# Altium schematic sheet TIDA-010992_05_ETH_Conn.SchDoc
size 431 x 279 mm; Date: Not shown in title block; ApprovedBy: Not shown in title block; CheckedBy: Not shown in title block; Author: Not shown in title block; CompanyName: Not shown in title block; Engineer: Not shown in title block; Organization: Not shown in title block; Address1: Not shown in title block; Address2: Not shown in title block; Address3: Not shown in title block; Address4: Not shown in title block; DocumentNumber: 5; Revision: Use project parameter SCH_Rev; SheetNumber: 5; SheetTotal: 13; PageSetup: Record=PageOptions¦CenterHorizontal=True¦CenterVertical=True¦PrintScale=1.00¦XCorrection=1.00¦YCorrection=1.00¦PrintKind=0¦BorderSize=5000000¦LeftOffset=0¦BottomOffset=0¦Orientation=2¦PaperLength=1000¦PaperWidth=1000¦Scale=100¦PaperSource=15¦PrintQuality=600¦MediaType=1¦DitherType=10¦PaperKind=Letter¦PrintScaleMode=1
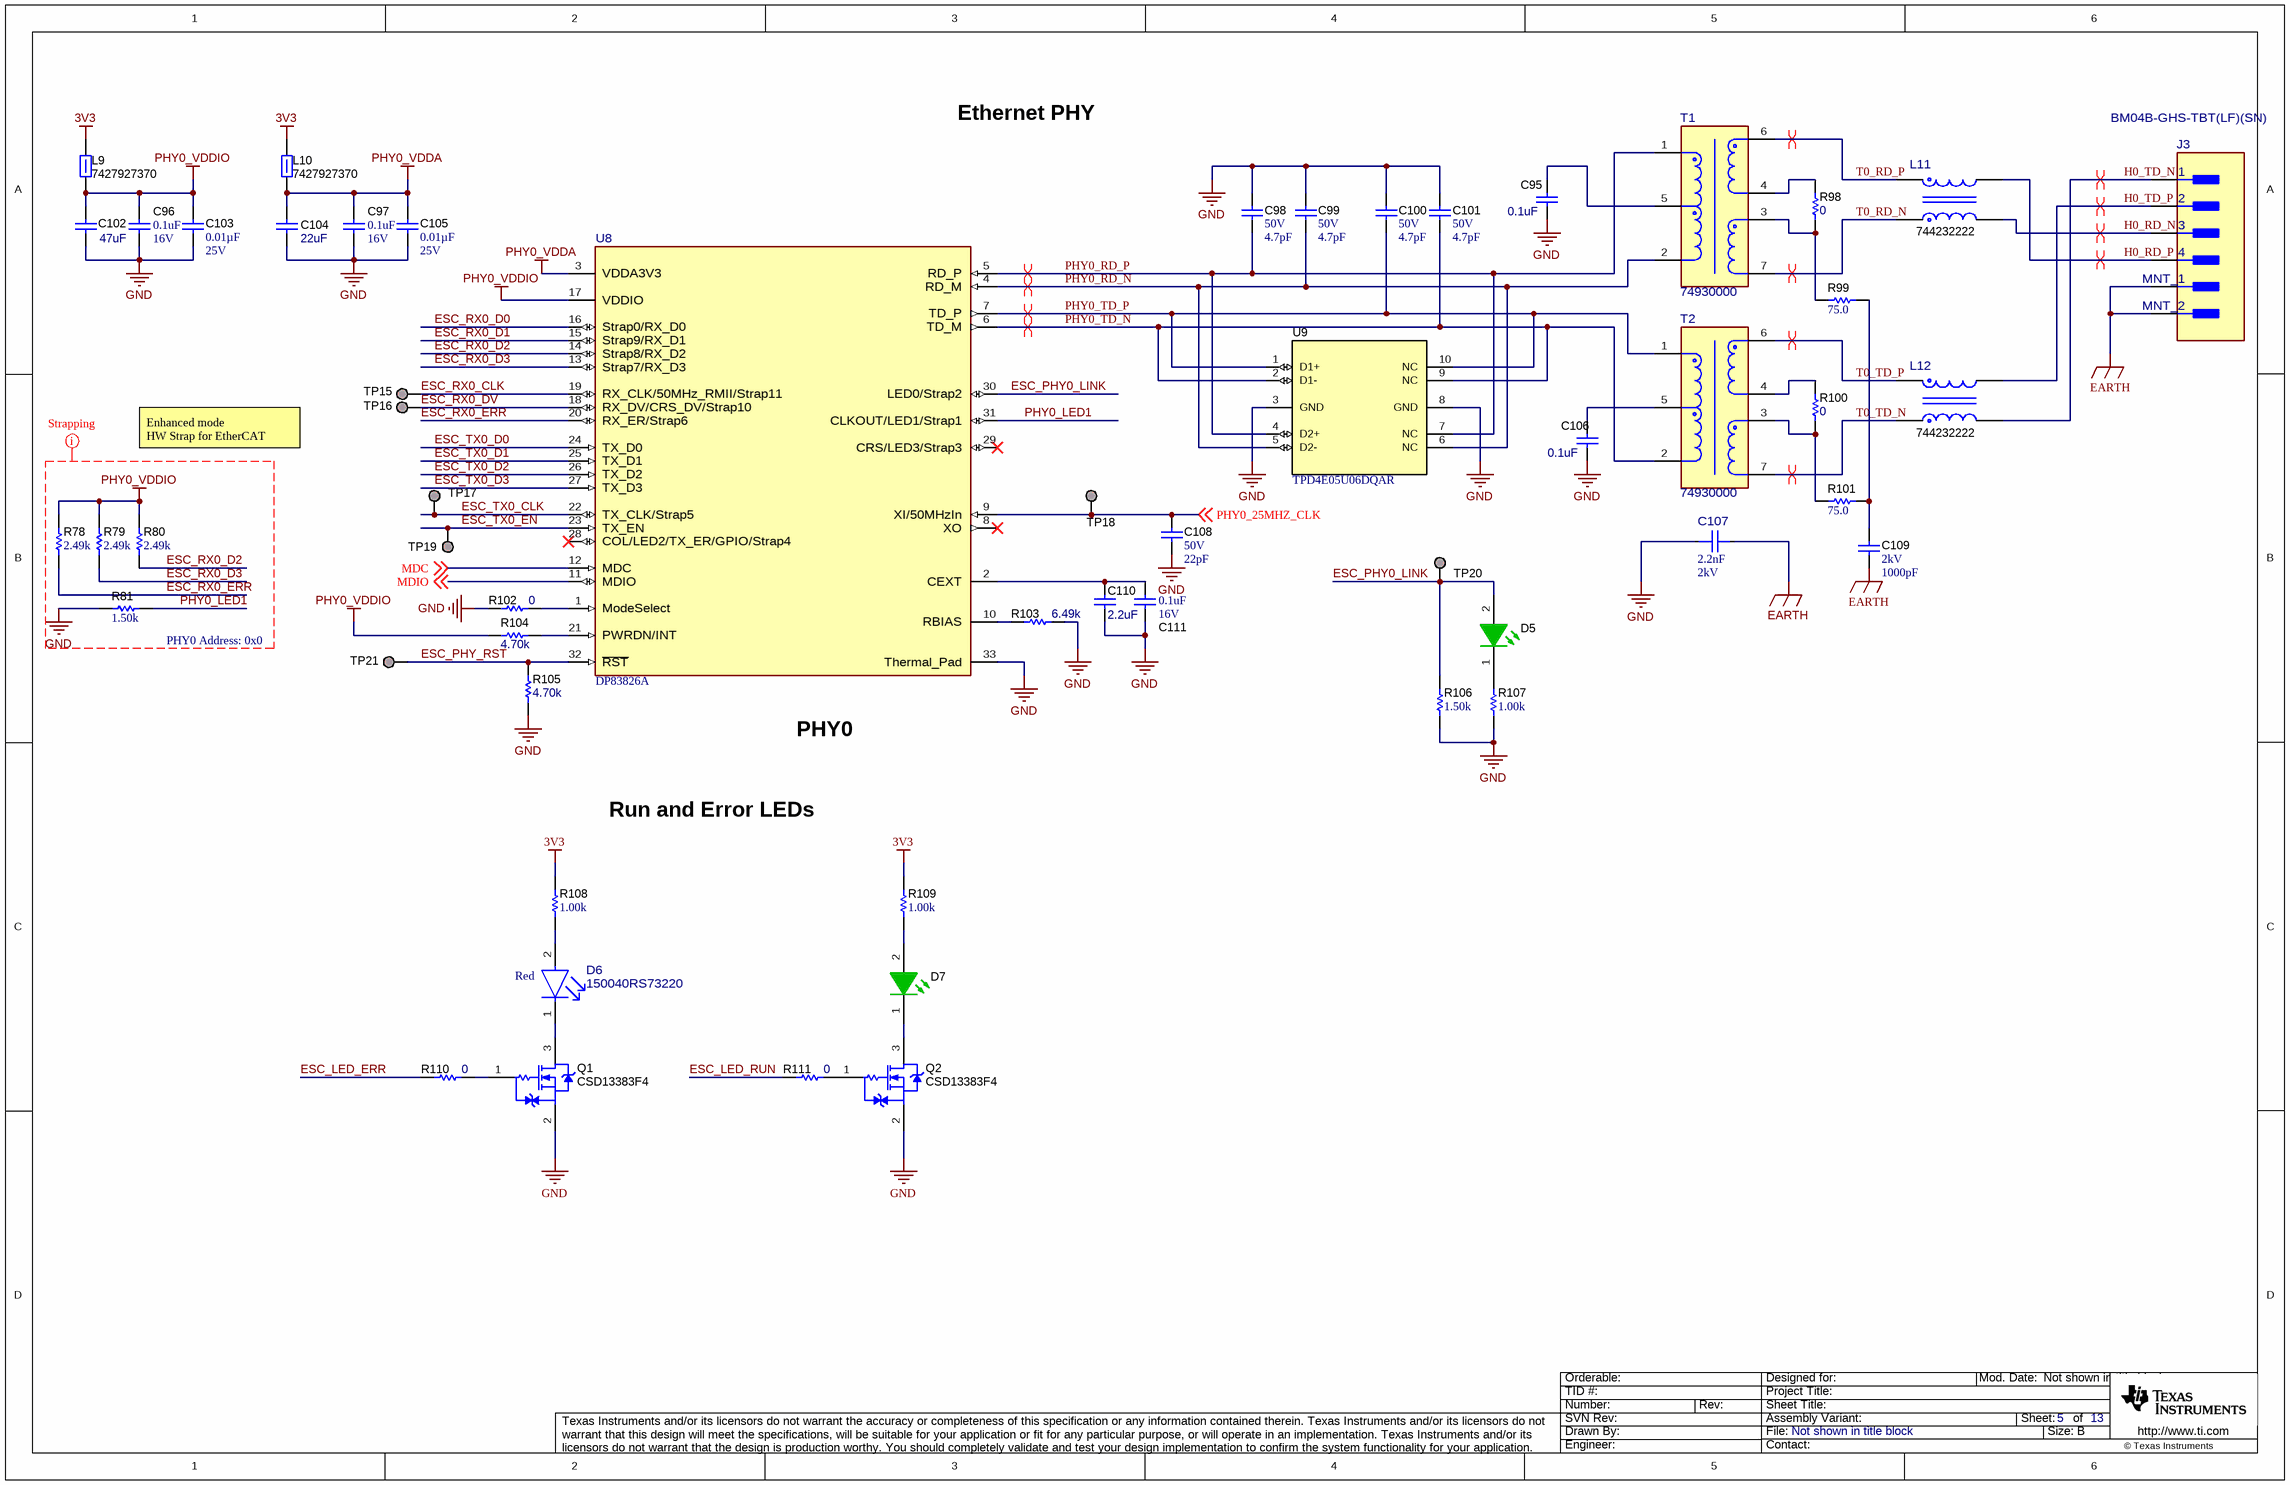
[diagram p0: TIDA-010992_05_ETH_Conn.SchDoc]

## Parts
C95  ValueDisplayed: 0.1uF  [0402]  (hidden comment: 885012205037)
C96  VDC_V: 16V  ValueDisplayed: 0.1uF  [0201]  (hidden comment: GRM033Z71C104KE14D)
C97  VDC_V: 16V  ValueDisplayed: 0.1uF  [0201]  (hidden comment: GRM033Z71C104KE14D)
C98  VDC_V: 50V  ValueDisplayed: 4.7pF  [0201_033]  (hidden comment: GRM0335C1H4R7BA01D)
C99  VDC_V: 50V  ValueDisplayed: 4.7pF  [0201_033]  (hidden comment: GRM0335C1H4R7BA01D)
C100  VDC_V: 50V  ValueDisplayed: 4.7pF  [0201_033]  (hidden comment: GRM0335C1H4R7BA01D)
C101  VDC_V: 50V  ValueDisplayed: 4.7pF  [0201_033]  (hidden comment: GRM0335C1H4R7BA01D)
C102  ValueDisplayed: 47uF  [0603]  (hidden comment: GRM188R60J476ME15D)
C103  ValueDisplayed: 0.01µF  VDC_V: 25V  [0201]  (hidden comment: GRM033R71E103KE14D)
C104  ValueDisplayed: 22uF  [0603]  (hidden comment: GRM188R61A226ME15D)
C105  ValueDisplayed: 0.01µF  VDC_V: 25V  [0201]  (hidden comment: GRM033R71E103KE14D)
C106  ValueDisplayed: 0.1uF  [0402]  (hidden comment: 885012205037)
C107  ValueDisplayed: 2.2nF  VDC_V: 2kV  [FP-1206Y2K00222KET_1206-MFG]  (hidden comment: 1206Y2K00222KET)
C108  VDC_V: 50V  ValueDisplayed: 22pF  [0402]  (hidden comment: CL05C220JB5NNNC)
C109  VDC_V: 2kV  ValueDisplayed: 1000pF  [1206_180]  (hidden comment: C1206C102KGRACAUTO)
C110  ValueDisplayed: 2.2uF  [0402_065]  (hidden comment: C1005X5R1V225K050BC)
C111  VDC_V: 16V  ValueDisplayed: 0.1uF  [0201]  (hidden comment: GRM033Z71C104KE14D)
D5  150040GS73240  [WL-SMCC_0402_Green]  (value not drawn)
D6  150040RS73220  Color: Red  [FP-150040RS73220_0402-MFG]
D7  150040GS73240  [WL-SMCC_0402_Green]  (value not drawn)
J3  BM04B-GHS-TBT(LF)(SN)  [FP-BM04B-GHS-TBT(LF)(SN)_HDR4-MFG]
L9  7427927370  [0402]
L10  7427927370  [0402]
L11  744232222  [FP-744232222_SMT4_3MM2_1MM6-MFG]
L12  744232222  [FP-744232222_SMT4_3MM2_1MM6-MFG]
Q1  CSD13383F4  [YJC0003A]
Q2  CSD13383F4  [YJC0003A]
R78  ValueDisplayed: 2.49k  [0201]  (hidden comment: RC0201FR-072K49L)
R79  ValueDisplayed: 2.49k  [0201]  (hidden comment: RC0201FR-072K49L)
R80  ValueDisplayed: 2.49k  [0201]  (hidden comment: RC0201FR-072K49L)
R81  ValueDisplayed: 1.50k  [0201]  (hidden comment: RK73H1HTTC1501F)
R98  ValueDisplayed: 0  [0402]  (hidden comment: CRCW04020000Z0EDHP)
R99  ValueDisplayed: 75.0  [0402]  (hidden comment: CRCW040275R0FKED)
R100  ValueDisplayed: 0  [0402]  (hidden comment: CRCW04020000Z0EDHP)
R101  ValueDisplayed: 75.0  [0402]  (hidden comment: CRCW040275R0FKED)
R102  ValueDisplayed: 0  [0402]  (hidden comment: CRCW04020000Z0EDHP)
R103  ValueDisplayed: 6.49k  [0402]  (hidden comment: CRCW04026K49FKED)
R104  ValueDisplayed: 4.70k  [0402]  (hidden comment: CRG0402F4K7)
R105  ValueDisplayed: 4.70k  [0402]  (hidden comment: CRG0402F4K7)
R106  ValueDisplayed: 1.50k  [0402]  (hidden comment: CRCW04021K50FKED)
R107  ValueDisplayed: 1.00k  [0402]  (hidden comment: CRCW04021K00FKED)
R108  ValueDisplayed: 1.00k  [0402]  (hidden comment: RC0402FR-071KL)
R109  ValueDisplayed: 1.00k  [0402]  (hidden comment: RC0402FR-071KL)
R110  ValueDisplayed: 0  [0402]  (hidden comment: CRCW04020000Z0EDHP)
R111  ValueDisplayed: 0  [0402]  (hidden comment: CRCW04020000Z0EDHP)
T1  74930000  [FP-74930000_SMT_4MM7_3MM22-MFG]
T2  74930000  [FP-74930000_SMT_4MM7_3MM22-MFG]
TP15  TESTPOINT  [TP_25MIL-SMT]  (value not drawn)  (no BOM)
TP16  TESTPOINT  [TP_25MIL-SMT]  (value not drawn)  (no BOM)
TP17  TESTPOINT  [TP_25MIL-SMT]  (value not drawn)  (no BOM)
TP18  TP_SM_1MM  [TP_SM_1MM]  (value not drawn)  (no BOM)
TP19  TESTPOINT  [TP_25MIL-SMT]  (value not drawn)  (no BOM)
TP20  TESTPOINT  [TP_25MIL-SMT]  (value not drawn)  (no BOM)
TP21  TESTPOINT  [TP_25MIL-SMT]  (value not drawn)  (no BOM)
U8  DP83826A  [RHB0032M-MFG]
U9  TPD4E05U06DQAR  [DQA0010A]

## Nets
3V3: L9.2 L10.2 R108.2 R109.2
EARTH: C107.2 C109.2 J3.5(MNT_1) J3.6(MNT_2)
GND: C95.2 C96.2 C97.2 C98.1 C99.1 C100.1 C101.1 C102.2 C103.2 C104.2 C105.2 C106.2 C107.1 C108.2 C110.2 C111.2 Q1.2(S) Q2.2(S) R81.1 R102.1 R103.2 R105.1 R106.2 R107.1 U8.33(Thermal_Pad) U9.3(GND) U9.8(GND)
PHY0_VDDA: C97.1 C104.1 C105.1 L10.1 U8.3(VDDA3V3)
PHY0_VDDIO: C96.1 C102.1 C103.1 L9.1 R78.2 R79.2 R80.2 R104.1 U8.17(VDDIO)
ESC_LED_ERR: R110.1
ESC_LED_RUN: R111.1
ESC_PHY0_LINK: D5.2(A) R106.1 TP20.1 U8.30(LED0/Strap2)
ESC_PHY_RST: R105.2 TP21.1 U8.32(~{RST})
ESC_RX0_CLK: TP15.1 U8.19(RX_CLK/50MHz_RMII/Strap11)
ESC_RX0_D0: U8.16(Strap0/RX_D0)
ESC_RX0_D1: U8.15(Strap9/RX_D1)
ESC_RX0_D2: R80.1 U8.14(Strap8/RX_D2)
ESC_RX0_D3: R79.1 U8.13(Strap7/RX_D3)
ESC_RX0_DV: TP16.1 U8.18(RX_DV/CRS_DV/Strap10)
ESC_RX0_ERR: R78.1 U8.20(RX_ER/Strap6)
ESC_TX0_CLK: TP17.1 U8.22(TX_CLK/Strap5)
ESC_TX0_D0: U8.24(TX_D0)
ESC_TX0_D1: U8.25(TX_D1)
ESC_TX0_D2: U8.26(TX_D2)
ESC_TX0_D3: U8.27(TX_D3)
ESC_TX0_EN: TP19.1 U8.23(TX_EN)
H0_RD_N: J3.3 L11.2
H0_RD_P: J3.4 L11.3
H0_TD_N: J3.1 L12.2
H0_TD_P: J3.2 L12.3
MDC: U8.12(MDC) ; off-sheet MDC
MDIO: U8.11(MDIO) ; off-sheet MDIO
PHY0_25MHZ_CLK: C108.1 TP18.1 U8.9(XI/50MHzIn) ; off-sheet PHY0_25MHZ_CLK
PHY0_LED1: R81.2 U8.31(CLKOUT/LED1/Strap1)
PHY0_RD_N: C99.2 T1.2 U8.4(RD_M) U9.5(D2-) U9.6(NC)
PHY0_RD_P: C98.2 T1.1 U8.5(RD_P) U9.4(D2+) U9.7(NC)
PHY0_TD_N: C101.2 T2.2 U8.6(TD_M) U9.2(D1-) U9.9(NC)
PHY0_TD_P: C100.2 T2.1 U8.7(TD_P) U9.1(D1+) U9.10(NC)
T0_RD_N: L11.1 T1.7
T0_RD_P: L11.4 T1.6
T0_TD_N: L12.1 T2.7
T0_TD_P: L12.4 T2.6
NetC95_1: C95.1 T1.5
NetC106_1: C106.1 T2.5
NetC109_1: C109.1 R99.2 R101.2
NetC110_1: C110.1 C111.1 U8.2(CEXT)
NetD5_1: D5.1(K) R107.2
NetD6_1: D6.1(CATHODE) Q1.3(D)
NetD6_2: D6.2(ANODE) R108.1
NetD7_1: D7.1(K) Q2.3(D)
NetD7_2: D7.2(A) R109.1
NetQ1_1: Q1.1(G) R110.2
NetQ2_1: Q2.1(G) R111.2
NetR98_1: R98.1 R99.1 T1.3
NetR98_2: R98.2 T1.4
NetR100_1: R100.1 R101.1 T2.3
NetR100_2: R100.2 T2.4
NetR102_2: R102.2 U8.1(ModeSelect)
NetR103_1: R103.1 U8.10(RBIAS)
NetR104_2: R104.2 U8.21(PWRDN/INT)

Not connected (* = marked no-connect by the designer): U8 8(XO)* 28(COL/LED2/TX_ER/GPIO/Strap4)* 29(CRS/LED3/Strap3)*

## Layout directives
differential pair: H0_RD_N, H0_RD_P, H0_TD_N, H0_TD_P, PHY0_RD_N, PHY0_RD_P, PHY0_TD_N, PHY0_TD_P, T0_RD_N, T0_RD_P, T0_TD_N, T0_TD_P
mark named Strapping: ESC_RX0_D2, ESC_RX0_D3, ESC_RX0_ERR, GND, PHY0_LED1, PHY0_VDDIO

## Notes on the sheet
- Ethernet PHY
- Enhanced mode
  HW Strap for EtherCAT setting
- (near R81) PHY0 Address: 0x0
- PHY0
- Run and Error LEDs

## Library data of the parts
C95 C106 = CMP-0006228-2: CAP, CERM, 0.1 uF, 16 V, +/- 10%, X7R, 0402; Manufacturer: Wurth Elektronik; TaMin_C: -55°C; Polarized: N; SizeAreaWB_mm2: 3; Value1: Unknown; U/M: EA; Value: 0.1uF; TaMax_C: 125°C; SizeZ_mm: 0.6; SizeX_mm: 1; SizeY_mm: 0.5; Value2: 16V; Cap_F: 100nF; AEC Category: Q200
C96 C97 C111 = CMP-0064970-1: CAP, CERM, 0.1 uF, 16 V,+/- 10%, X7R, 0201; Manufacturer: MuRata; TaMin_C: -55°C; Polarized: N; SizeAreaWB_mm2: 2.08; Value1: Unknown; U/M: EA; Value: 0.1uF; TaMax_C: 125°C; SizeZ_mm: 0.26; SizeX_mm: 0.6; SizeY_mm: 0.3; SizeArea_mm2: 0.18; Cap_F: 100nF; AEC Category: Q200
C98-C101 = CMP-0080076-1: CAP, CERM, 4.7 pF, 50 V,+/- 3%, C0G/NP0, 0201; Manufacturer: MuRata; TaMin_C: -55°C; Polarized: N; SizeAreaWB_mm2: 2.08; U/M: EA; Value: 4.7pF; TaMax_C: 125°C; SizeZ_mm: 0.33; SizeX_mm: 0.6; SizeY_mm: 0.3; Cap_Case: 0201; SizeArea_mm2: 0.18; AEC Category: Q200
C102 = CMP-0007313-5: CAP, CERM, 47 uF, 6.3 V, +/- 20%, X5R, 0603; Manufacturer: MuRata; TaMin_C: -55°C; Polarized: N; SizeAreaWB_mm2: 4.68; Value1: Unknown; U/M: EA; Value: 47uF; TaMax_C: 85°C; SizeZ_mm: 1; SizeX_mm: 1.6; SizeY_mm: 0.8; Value2: 6.3V; SizeArea_mm2: 1.28; Cap_F: 47µF; AEC Category: Q200
C103 C105 = CMP-0860568-1: CAP, CERM, 0.01 µF, 25 V,+/- 10%, X7R, 0201; Manufacturer: MuRata; U/M: EA; TaMax_C: 125°C; SizeZ_mm: 0.26; AEC Qualified: N; TaMin_C: -55°C; SizeY_mm: 0.3; AEC Category: Q200; SizeAreaWB_mm2: 2.08; Cap_F: 10nF; SizeX_mm: 0.6; Value: 0.01uF; SizeArea_mm2: 0.18
C104 = CMP-0007324-5: CAP, CERM, 22 uF, 10 V, +/- 20%, X5R, 0603; Manufacturer: MuRata; TaMin_C: -55°C; Polarized: N; SizeAreaWB_mm2: 4.68; Value1: Unknown; U/M: EA; Value: 22uF; TaMax_C: 85°C; SizeZ_mm: 1; SizeX_mm: 1.6; SizeY_mm: 0.8; Value2: 10V; SizeArea_mm2: 1.28; Cap_F: 22µF; AEC Category: Q200
C107 = CMP-0090879-1: 2200pF ±10% 2000V (2kV) Ceramic Capacitor X7R (2R1) 1206 (3216 Metric); Manufacturer: Knowles Syfer; TempCo: 15%; AEC Grade: Grade 1; AEC Qualified: Yes; SizeZ_mm: 1.7mm; Value: 2.2nF
C108 = CMP-0085851-1: CAP, CERM, 22 pF, 50 V,+/- 5%, C0G/NP0, 0402; Manufacturer: Walsin; AEC Qualified: N; TaMax_C: 125°C; SizeX_mm: 1; Value: 22pF; SizeZ_mm: 0.6; AEC Category: Q200; TaMin_C: -55°C; SizeArea_mm2: 0.5; SizeAreaWB_mm2: 3; U/M: EA
C109 = CMP-0008579-2: CAP, CERM, 1000 pF, 2000 V, +/- 10%, X7R, AEC-Q200 Grade 1, 1206; Manufacturer: Kemet; TaMin_C: -55°C; Polarized: N; SizeAreaWB_mm2: 10.92; Value1: Unknown; U/M: EA; Value: 1000pF; TaMax_C: 125°C; SizeZ_mm: 1.8; SizeX_mm: 3.2; SizeY_mm: 1.6; Cap_Case: 1206; Value2: 2000V; SizeArea_mm2: 5.12; AEC Qualified: Y; Cap_F: 1nF; AEC Grade: 1; AEC Category: Q200
C110 = CMP-0006283-2: CAP, CERM, 2.2 uF, 35 V, +/- 10%, X5R, 0402; Manufacturer: TDK; TaMin_C: -55°C; ESR_ohm: 5.925m; Polarized: N; SizeAreaWB_mm2: 3; Value1: 0.005925 ohm; U/M: EA; Value: 2.2uF; TaMax_C: 85°C; SizeZ_mm: 0.65; SizeX_mm: 1; SizeY_mm: 0.5; Value2: 35V; Cap_F: 2.2µF; IRMS_A: 2.0559A; AEC Category: Q200
D5 D7 = CMP-0081765-2: LED, Green, SMD; Manufacturer: Wurth Elektronik; Vr_V: 5V; Io_A: 20mA; Tjmax_C: 95°C; Ir_A: 10µA; Power_TotalModule: 99mW; Value2: 3.2V; SizeArea_mm2: 0.5; SizeX_mm: 1; Value1: 0.099W; Angle: 120; Type: InGaN; SizeAreaWB_mm2: 3
D6 = CMP-0122246-1: Red 624nm LED Indication - Discrete 2V 0402 (1005 Metric); Manufacturer: Wurth; Angle: 120°; LambdaP: 632nm; Power_TotalModule: 48mW; SizeZ_mm: 0.35mm; Tjmax_C: 115°C; Vr_V: 5V; AEC Qualified: No; Forward Current: 20mA; Led Orientation: Top View; Luminous Intensity: 110mcd
J3 = CMP-0125599-1: Connector Header Surface Mount 4 position 0.049" (1.25mm); Manufacturer: JST; ContactFinish: Tin; Current_A: 1A; Row_Count: 1; Voltage_V: 50V; AEC Qualified: No; Conn Gender: Male; Conn Orientation: Vertical; SizeZ_mm: 4.05mm
L9 L10 = CMP-0003238-1: Ferrite Bead, 70 ohm @ 100 MHz, 1.2 A, 0402; Manufacturer: Wurth Elektronik; Ztyp@1GHz_Ohm: 122.92; ZTyp@100MHz_Ohm: 70; SizeAreaWB_mm2: 3; DCR_ohm: 90m; Value1: 0.09 ohm; Value: 70 ohm; Imax_A: 1.2A; SizeZ_mm: 0.6; SizeX_mm: 1; SizeY_mm: 0.5
L11 L12 = CMP-0092201-1: 2 Line Common Mode Choke Surface Mount 200mA DCR 1.2Ohm; Manufacturer: Wurth; TaMin_C: -40°C; AEC Qualified: Yes; AEC Grade: Grade 1; SizeZ_mm: 2mm; Ind_H: 2.578µH; Impedance At Frequency: 2200Ω @ 100MHz; TaMax_C: +85°C; DCR_ohm: 1.2
Q1 Q2 = CMP-0000198-1: MOSFET, N-CH, 12 V, 2.9 A, YJC0003A (PICOSTAR-3); Alternate Manufacturer: None; Manufacturer: Texas Instruments; SizeZ_mm: 0.35; ChType: N; Value2: 2 nC; Value1: 0.04; VdsMax_V: 12V; SizeX_mm: 1.035; SizeY_mm: 0.635; Vgs_V: 10V; Value: 12V; Rdson45_ohm: 44m; SizeArea_mm2: 0.657225; AEC Category: Q101; IdsMax_A: 2.9A; SizeAreaWB_mm2: 3.327225; U/M: EA; QgTyp_nC: 2
R78-R80 = CMP-0027562-1: RES, 2.49 k, 1%, 0.05 W, 0201; Manufacturer: Yageo America; Power_W: 50mW; TempCo: 200 ppm/C; Value_Code: 2k49; U/M: EA; Value: 2.49k; EIA_Code: E96; SizeX_mm: 0.6; SizeY_mm: 0.3; SizeZ_mm: 0.26; Value2: 0.05W; SizeArea_mm2: 0.18; AEC Qualified: N; VDC_V: 25V; AEC Category: Q200
R81 = CMP-0028124-1: RES, 1.50 k, 1%, 0.05 W, AEC-Q200 Grade 0, 0201; Manufacturer: KOA Speer; Power_W: 50mW; TempCo: 200 ppm/C; Value_Code: 1k50; U/M: EA; Value: 1.50k; EIA_Code: E96; Res_ohm: 1.5k; SizeX_mm: 0.6; SizeY_mm: 0.3; SizeZ_mm: 0.26; Value2: 0.05W; SizeArea_mm2: 0.18; AEC Qualified: Y; VDC_V: 25V; AEC Grade: 0; AEC Category: Q200
R98 R100 R102 R110 R111 = CMP-0081856-1: RES, 0, 0%, 0.2 W, AEC-Q200 Grade 0, 0402; Manufacturer: Vishay-Dale; SizeAreaWB_mm2: 3; SizeArea_mm2: 0.5; AEC Qualified: Y; AEC Category: Q200; Value: 0; SizeZ_mm: 0.6; Power_W: 200mW; VDC_V: 50V; Value2: 0.2W; SizeX_mm: 1
R99 R101 = CMP-0026544-2: RES, 75.0, 1%, 0.063 W, AEC-Q200 Grade 0, 0402; Manufacturer: Vishay-Dale; Power_W: 63mW; TempCo: 100 ppm/C; Value_Code: 75R0; Value: 75.0; EIA_Code: E96; Res_ohm: 75; SizeX_mm: 1; SizeY_mm: 0.5; SizeZ_mm: 0.6; Value2: 0.063W; AEC Qualified: Y; VDC_V: 50V; AEC Category: Q200; AEC Grade: 0
R103 = CMP-0026515-2: RES, 6.49 k, 1%, 0.063 W, AEC-Q200 Grade 0, 0402; Manufacturer: Vishay-Dale; Power_W: 63mW; TempCo: 100 ppm/C; Value_Code: 6k49; Value: 6.49k; EIA_Code: E96; SizeX_mm: 1; SizeY_mm: 0.5; SizeZ_mm: 0.6; Value2: 0.063W; AEC Qualified: Y; VDC_V: 50V; AEC Category: Q200; AEC Grade: 0
R104 R105 = CMP-0026631-1: RES, 4.70 k, 1%, 0.063 W, 0402; Manufacturer: TE Connectivity; Power_W: 63mW; TempCo: 100 ppm/C; Value_Code: 4k70; U/M: EA; Value: 4.70k; Res_ohm: 4.7k; SizeX_mm: 1; SizeY_mm: 0.5; SizeZ_mm: 0.6; Value2: 0.063W; AEC Qualified: N; AEC Category: Q200
R106 = CMP-0026088-3: RES, 1.50 k, 1%, 0.063 W, AEC-Q200 Grade 0, 0402; Manufacturer: Vishay-Dale; Power_W: 63mW; TempCo: 100 ppm/C; Value_Code: 1k50; Value: 1.50k; EIA_Code: E96; Res_ohm: 1.5k; SizeX_mm: 1; SizeY_mm: 0.5; SizeZ_mm: 0.6; Value2: 0.063W; AEC Qualified: Y; VDC_V: 50V; AEC Category: Q200; AEC Grade: 0
R107 = CMP-0026071-3: RES, 1.00 k, 1%, 0.063 W, AEC-Q200 Grade 0, 0402; Manufacturer: Vishay-Dale; Power_W: 63mW; TempCo: 100 ppm/C; Value_Code: 1k00; Value: 1.00k; EIA_Code: E96; Res_ohm: 1k; SizeX_mm: 1; SizeY_mm: 0.5; SizeZ_mm: 0.6; Value2: 0.063W; AEC Qualified: Y; VDC_V: 50V; AEC Category: Q200; AEC Grade: 0
R108 R109 = CMP-0026725-1: RES, 1.00 k, 1%, 0.0625 W, 0402; Manufacturer: Yageo America; Power_W: 62.5mW; TempCo: 100 ppm/C; Value_Code: 1k00; U/M: EA; Value: 1.00k; EIA_Code: E96; Res_ohm: 1k; SizeX_mm: 1; SizeY_mm: 0.5; SizeZ_mm: 0.6; AEC Qualified: N; VDC_V: 50V; AEC Category: Q200
T1 T2 = CMP-0088807-1: 350µH  Pulse Transformer 1:1 Surface Mount; Manufacturer: Wurth Electronics; Voltage_Isolation_Vrms: 1500Vrms; SizeZ_mm: 2.9mm; AEC Qualified: No; DCR_ohm: 4.5; Insertion Loss: -1dB; Return Loss: -10dB
TP15-TP17 TP19-TP21 = CMP-0078143-3: TEST POINT.  No entry in BOM.
TP18 = CMP-0003825-1: 1mm Test Point, SMT; Manufacturer: Any
U8 = CMP-0124715-2: Deterministic, Low-Latency, Low-Power, 10/100 Mbps, Industrial Ethernet PHY; Manufacturer: Texas Instruments; SizeZ_mm: 1mm; AEC Qualified: No; Data Rate: 100Mbits/s; Interface: Ethernet,Other; Max Supply Voltage: 3.6V; Min Supply Voltage: 1.62V; Number Of Channels: 1; Simplex Duplex: Full-Duplex; Standoff Height: 0mm; TaMax_C: +85°C; TaMin_C: -40°C; AEC Category: Q200; CompType: IC
U9 = CMP-0073613-3: 4-Channel Ultra-Low-Capacitance IEC ESD Protection Diode, DQA0010A (USON-10); Alternate Manufacturer: Texas Instruments; Green_Lifecycle: Active; SizeAreaWB_mm2: 7.0; Green_REACh: Passed; SizeZ_mm: 0.55; SizeX_mm: 1.0; SizeY_mm: 2.5; CompType: IC; AEC Category: Q200; AEC Qualified: N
